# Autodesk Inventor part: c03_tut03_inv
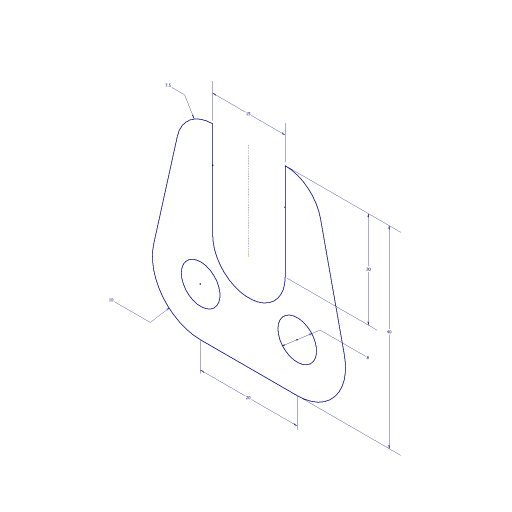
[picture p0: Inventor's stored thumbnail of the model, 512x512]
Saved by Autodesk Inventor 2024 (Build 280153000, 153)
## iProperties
Created: 2017-04
Part Number: c03_tut03_inv
Material: Generic
Document SubType Name: Modeling
Designer: CADCIM 00
Density: 1 g/cm^3
Appearance: Default
Author: CADCIM 00
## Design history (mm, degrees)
sketch "Sketch1"
  geometry: L1 (-10, -20)-(10, -20); L2 (19.756, -7.805)-(14.817, 14.146); L3 (7.5, 20)-(7.5, 0); L4 (-7.5, 0)-(-7.5, 20); L5 (-14.817, 14.146)-(-19.756, -7.805); L6 (0, 0)-(0, 20); C1 r 4 at (-10, -10); C2 r 4 at (10, -10); A1 r 10 centre (10, -10) between (10, -20) and (19.756, -7.805); A2 r 7.5 centre (7.5, 12.5) between (14.817, 14.146) and (7.5, 20); A3 r 7.5 centre (0, 0) between (-7.5, 0) and (7.5, 0); A4 r 7.5 centre (-7.5, 12.5) between (-7.5, 20) and (-14.817, 14.146); A5 r 10 centre (-10, -10) between (-19.756, -7.805) and (-10, -20); 1 further point
  constraints: 12 end point, 10 point on circle, 8 tangent, 7 centre point, 3 coincident, 3 equal radius, 2 equal length, 2 point on line, 1 horizontal, 1 horizontal alignment, 1 parallel, 1 perpendicular, 1 vertical, 3 other
  dimensions: "d0" = 20 distance of L1.start L1.end; "d1" = 7.5 radius of A2; "d2" = 10 radius of A1; "d3" = 15 distance between parallel lines of L4 L3; "d5" = 40 distance from line of L1 L4.end; "d6" = 20 distance of L4.start L4.end; "d7" = 8 diameter of C1
